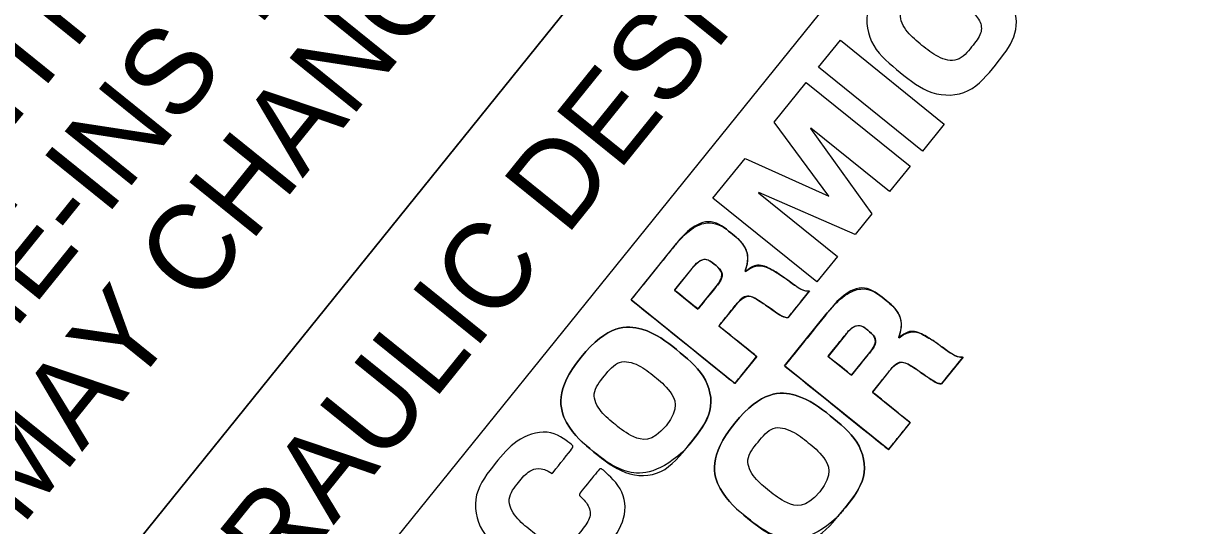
# Model space of a CAD drawing. Extents: x 1487832 to 1490056, y 498345 to 500343.
# Drawn here: x 1489651.2 to 1489727.7, y 499640.6 to 499673.5 of the extents above; entities that cross this region are included whole.
import ezdxf

# ---------------------------------------------------------------- set-up
doc = ezdxf.new("R2010")
doc.units = 0
doc.layers.add('Prop Grid Mask', color=7, linetype='Continuous')
doc.layers.add('Prop Horizontal Alignment Curve and Spiral Data', color=7, linetype='Continuous')

msp = doc.modelspace()

# ---------------------------------------------------------------- linework, layer by layer
at = {"layer": 'Prop Grid Mask'}
for p, q in [((1489703.231, 499670.595), (1489704.659, 499672.365)), ((1489704.659, 499672.365), (1489711.454, 499666.885)), ((1489710.027, 499665.115), (1489703.231, 499670.595)), ((1489700.329, 499666.996), (1489702.433, 499669.604)), ((1489702.433, 499669.604), (1489709.228, 499664.124)), ((1489703.916, 499662.173), (1489700.329, 499666.996)), ((1489702.726, 499666.619), (1489702.711, 499666.6)), ((1489702.711, 499666.6), (1489706.718, 499661.012)), ((1489707.885, 499662.459), (1489702.726, 499666.619)), ((1489711.454, 499666.885), (1489710.027, 499665.115)), ((1489696.323, 499662.028), (1489698.426, 499664.636)), ((1489698.426, 499664.636), (1489703.9, 499662.153)), ((1489709.228, 499664.124), (1489707.885, 499662.459)), ((1489703.118, 499656.548), (1489696.323, 499662.028)), ((1489699.319, 499662.393), (1489699.303, 499662.374)), ((1489699.303, 499662.374), (1489704.462, 499658.214)), ((1489705.628, 499659.66), (1489699.319, 499662.393)), ((1489703.9, 499662.153), (1489703.916, 499662.173)), ((1489706.718, 499661.012), (1489705.628, 499659.66)), ((1489704.462, 499658.214), (1489703.118, 499656.548)), ((1489698.435, 499657.246), (1489698.454, 499657.231)), ((1489702.642, 499655.957), (1489701.23, 499654.207)), ((1489708.48, 499652.914), (1489708.499, 499652.899)), ((1489712.687, 499651.626), (1489711.275, 499649.875))]:
    msp.add_line(p, q, dxfattribs=at)
for points in [[(1489502.46, 499445.87), (1489705.455, 499697.585), (1489601.093, 499781.747), (1489398.098, 499530.033)], [(1489651.998, 499610.518), (1489715.609, 499689.396), (1489705.455, 499697.585), (1489641.844, 499618.707)], [(1489651.998, 499610.518), (1489715.609, 499689.396), (1489756.18, 499656.677), (1489692.569, 499577.8)]]:
    msp.add_lwpolyline(points, close=True, dxfattribs=at)
for points in [[(1489703.231, 499670.595), (1489704.659, 499672.365), (1489711.454, 499666.885), (1489710.027, 499665.115), (1489703.231, 499670.595)], [(1489696.323, 499662.028), (1489698.426, 499664.636), (1489703.9, 499662.153), (1489703.916, 499662.173), (1489700.329, 499666.996), (1489702.433, 499669.604), (1489709.228, 499664.124), (1489707.885, 499662.459), (1489702.726, 499666.619), (1489702.711, 499666.6), (1489706.718, 499661.012), (1489705.628, 499659.66), (1489699.319, 499662.393), (1489699.303, 499662.374), (1489704.462, 499658.214), (1489703.118, 499656.548), (1489696.323, 499662.028)], [(1489697.796, 499655.012), (1489696.713, 499653.67), (1489699.188, 499651.675), (1489697.761, 499649.904), (1489690.965, 499655.385), (1489693.759, 499658.849)], [(1489694.947, 499657.42), (1489693.811, 499656.011), (1489695.343, 499654.775), (1489696.54, 499656.26)], [(1489707.84, 499650.681), (1489706.758, 499649.339), (1489709.233, 499647.343), (1489707.805, 499645.573), (1489701.01, 499651.053), (1489703.804, 499654.517)], [(1489704.992, 499653.088), (1489703.855, 499651.68), (1489705.387, 499650.444), (1489706.585, 499651.929)]]:
    msp.add_lwpolyline(points, dxfattribs=at)
for points in [[(1489711.408, 499675.767), (1489710.645, 499676.223), (1489709.854, 499675.982), (1489709.255, 499675.24), (1489708.334, 499674.098), (1489708.989, 499672.847), (1489709.998, 499672.033), (1489711.007, 499671.219), (1489712.369, 499670.844), (1489713.29, 499671.986), (1489713.958, 499672.814), (1489713.866, 499673.673), (1489713.14, 499674.37), (1489713.14, 499674.37), (1489714.567, 499676.139), (1489714.567, 499676.139), (1489716.242, 499674.632), (1489716.233, 499672.519), (1489714.844, 499670.796), (1489713.186, 499668.74), (1489710.541, 499668.674), (1489708.571, 499670.263), (1489706.601, 499671.852), (1489706.105, 499674.451), (1489707.763, 499676.506), (1489708.945, 499677.972), (1489711.16, 499678.809), (1489712.835, 499677.537), (1489712.835, 499677.537), (1489711.408, 499675.767), (1489711.408, 499675.767)], [(1489711.408, 499675.767), (1489710.645, 499676.223), (1489709.854, 499675.982), (1489709.255, 499675.24), (1489708.334, 499674.098), (1489708.989, 499672.847), (1489709.998, 499672.033), (1489711.007, 499671.219), (1489712.369, 499670.844), (1489713.29, 499671.986), (1489713.958, 499672.814), (1489713.866, 499673.673), (1489713.14, 499674.37), (1489713.14, 499674.37), (1489714.567, 499676.139), (1489714.567, 499676.139), (1489716.242, 499674.632), (1489716.233, 499672.519), (1489714.844, 499670.796), (1489713.186, 499668.74), (1489710.541, 499668.674), (1489708.571, 499670.263), (1489706.601, 499671.852), (1489706.105, 499674.451), (1489707.763, 499676.506), (1489708.945, 499677.972), (1489711.16, 499678.809), (1489712.835, 499677.537), (1489712.835, 499677.537), (1489711.408, 499675.767), (1489711.408, 499675.767)], [(1489690.965, 499655.385), (1489690.965, 499655.385), (1489693.759, 499658.849), (1489693.759, 499658.849), (1489694.726, 499660.048), (1489696.22, 499660.791), (1489697.591, 499659.686), (1489698.324, 499659.094), (1489698.735, 499658.183), (1489698.435, 499657.246), (1489698.435, 499657.246), (1489698.454, 499657.231), (1489698.454, 499657.231), (1489699.209, 499657.816), (1489700.186, 499657.373), (1489700.88, 499656.908), (1489701.181, 499656.697), (1489702.203, 499655.919), (1489702.642, 499655.957), (1489702.642, 499655.957), (1489701.23, 499654.207), (1489701.23, 499654.207), (1489700.879, 499654.238), (1489700.189, 499654.747), (1489699.984, 499654.881), (1489699.26, 499655.386), (1489698.463, 499655.84), (1489697.796, 499655.012), (1489697.796, 499655.012), (1489696.713, 499653.67), (1489696.713, 499653.67), (1489696.713, 499653.67), (1489699.188, 499651.675), (1489699.188, 499651.675), (1489699.188, 499651.675), (1489697.761, 499649.904), (1489697.761, 499649.904), (1489697.761, 499649.904), (1489690.965, 499655.385), (1489690.965, 499655.385)], [(1489693.759, 499658.849), (1489694.726, 499660.048), (1489696.22, 499660.791), (1489697.591, 499659.686), (1489698.324, 499659.094), (1489698.735, 499658.183), (1489698.435, 499657.246)], [(1489695.343, 499654.775), (1489695.343, 499654.775), (1489696.54, 499656.26), (1489696.54, 499656.26), (1489696.97, 499656.793), (1489696.915, 499657.309), (1489696.401, 499657.724), (1489695.897, 499658.131), (1489695.346, 499657.915), (1489694.947, 499657.42), (1489694.947, 499657.42), (1489693.811, 499656.011), (1489693.811, 499656.011), (1489693.811, 499656.011), (1489695.343, 499654.775), (1489695.343, 499654.775)], [(1489696.54, 499656.26), (1489696.97, 499656.793), (1489696.915, 499657.309), (1489696.401, 499657.724), (1489695.897, 499658.131), (1489695.346, 499657.915), (1489694.947, 499657.42)], [(1489698.454, 499657.231), (1489699.209, 499657.816), (1489700.186, 499657.373), (1489700.88, 499656.908), (1489701.181, 499656.697), (1489702.203, 499655.919), (1489702.642, 499655.957)], [(1489701.23, 499654.207), (1489700.879, 499654.238), (1489700.189, 499654.747), (1489699.984, 499654.881), (1489699.26, 499655.386), (1489698.463, 499655.84), (1489697.796, 499655.012)], [(1489701.01, 499651.053), (1489701.01, 499651.053), (1489703.804, 499654.517), (1489703.804, 499654.517), (1489704.771, 499655.717), (1489706.265, 499656.46), (1489707.635, 499655.354), (1489708.368, 499654.763), (1489708.779, 499653.851), (1489708.48, 499652.914), (1489708.48, 499652.914), (1489708.499, 499652.899), (1489708.499, 499652.899), (1489709.253, 499653.484), (1489710.231, 499653.041), (1489710.924, 499652.576), (1489711.225, 499652.365), (1489712.247, 499651.588), (1489712.687, 499651.626), (1489712.687, 499651.626), (1489711.275, 499649.875), (1489711.275, 499649.875), (1489710.923, 499649.907), (1489710.234, 499650.415), (1489710.028, 499650.55), (1489709.305, 499651.055), (1489708.508, 499651.509), (1489707.84, 499650.681), (1489707.84, 499650.681), (1489706.758, 499649.339), (1489706.758, 499649.339), (1489706.758, 499649.339), (1489709.233, 499647.343), (1489709.233, 499647.343), (1489709.233, 499647.343), (1489707.805, 499645.573), (1489707.805, 499645.573), (1489707.805, 499645.573), (1489701.01, 499651.053), (1489701.01, 499651.053)], [(1489703.804, 499654.517), (1489704.771, 499655.717), (1489706.265, 499656.46), (1489707.635, 499655.354), (1489708.368, 499654.763), (1489708.779, 499653.851), (1489708.48, 499652.914)], [(1489687.696, 499651.624), (1489689.423, 499653.765), (1489691.969, 499653.707), (1489693.939, 499652.119), (1489695.909, 499650.53), (1489696.504, 499648.055), (1489694.777, 499645.913), (1489693.05, 499643.772), (1489690.506, 499643.829), (1489688.535, 499645.418), (1489686.565, 499647.007), (1489685.969, 499649.482), (1489687.696, 499651.624)], [(1489687.696, 499651.624), (1489689.423, 499653.765), (1489691.969, 499653.707), (1489693.939, 499652.119), (1489695.909, 499650.53), (1489696.504, 499648.055), (1489694.777, 499645.913), (1489694.541, 499645.62), (1489694.289, 499645.368), (1489694.025, 499645.156)], [(1489705.387, 499650.444), (1489705.387, 499650.444), (1489706.585, 499651.929), (1489706.585, 499651.929), (1489707.015, 499652.462), (1489706.96, 499652.977), (1489706.446, 499653.392), (1489705.941, 499653.799), (1489705.391, 499653.583), (1489704.992, 499653.088), (1489704.992, 499653.088), (1489703.855, 499651.68), (1489703.855, 499651.68), (1489703.855, 499651.68), (1489705.387, 499650.444), (1489705.387, 499650.444)], [(1489706.585, 499651.929), (1489707.015, 499652.462), (1489706.96, 499652.977), (1489706.446, 499653.392), (1489705.941, 499653.799), (1489705.391, 499653.583), (1489704.992, 499653.088)], [(1489708.499, 499652.899), (1489709.253, 499653.484), (1489710.231, 499653.041), (1489710.924, 499652.576), (1489711.225, 499652.365), (1489712.247, 499651.588), (1489712.687, 499651.626)], [(1489694.025, 499645.156), (1489692.364, 499643.816), (1489690.236, 499644.047), (1489688.535, 499645.418), (1489686.565, 499647.007), (1489685.969, 499649.482), (1489687.696, 499651.624)], [(1489693.255, 499647.141), (1489694.176, 499648.283), (1489693.52, 499649.535), (1489692.511, 499650.349), (1489691.502, 499651.162), (1489690.14, 499651.538), (1489689.219, 499650.396), (1489688.298, 499649.253), (1489688.954, 499648.002), (1489689.963, 499647.189), (1489690.972, 499646.375), (1489692.334, 499645.999), (1489693.255, 499647.141)], [(1489693.255, 499647.141), (1489694.176, 499648.283), (1489693.52, 499649.535), (1489692.511, 499650.349), (1489691.502, 499651.162), (1489690.14, 499651.538), (1489689.219, 499650.396), (1489688.298, 499649.253), (1489688.954, 499648.002), (1489689.963, 499647.189), (1489690.972, 499646.375), (1489692.334, 499645.999), (1489693.255, 499647.141)], [(1489711.275, 499649.875), (1489710.923, 499649.907), (1489710.234, 499650.415), (1489710.028, 499650.55), (1489709.305, 499651.055), (1489708.508, 499651.509), (1489707.84, 499650.681)], [(1489697.748, 499647.301), (1489699.475, 499649.443), (1489702.021, 499649.385), (1489703.991, 499647.797), (1489705.961, 499646.207), (1489706.557, 499643.732), (1489704.83, 499641.591), (1489703.103, 499639.449), (1489700.558, 499639.507), (1489698.587, 499641.096), (1489696.617, 499642.685), (1489696.021, 499645.16), (1489697.748, 499647.301)], [(1489697.748, 499647.301), (1489699.475, 499649.443), (1489702.021, 499649.385), (1489703.991, 499647.797), (1489705.961, 499646.207), (1489706.557, 499643.732), (1489704.83, 499641.591), (1489704.593, 499641.297), (1489704.341, 499641.045), (1489704.078, 499640.833)], [(1489685.807, 499644.021), (1489685.045, 499644.479), (1489684.253, 499644.237), (1489683.654, 499643.495), (1489682.733, 499642.353), (1489683.389, 499641.102), (1489684.398, 499640.288), (1489685.407, 499639.475), (1489686.769, 499639.099), (1489687.69, 499640.241), (1489688.358, 499641.069), (1489688.266, 499641.928), (1489687.539, 499642.624), (1489687.539, 499642.624), (1489688.967, 499644.395), (1489688.967, 499644.395), (1489690.641, 499642.887), (1489690.632, 499640.774), (1489689.243, 499639.051), (1489687.585, 499636.995), (1489684.941, 499636.929), (1489682.97, 499638.518), (1489681, 499640.106), (1489680.504, 499642.705), (1489682.162, 499644.761), (1489683.344, 499646.227), (1489685.559, 499647.064), (1489687.234, 499645.792), (1489687.234, 499645.792), (1489685.807, 499644.021), (1489685.807, 499644.021)], [(1489685.807, 499644.021), (1489685.045, 499644.479), (1489684.253, 499644.237), (1489683.654, 499643.495), (1489682.733, 499642.353), (1489683.389, 499641.102), (1489684.398, 499640.288), (1489685.407, 499639.475), (1489686.769, 499639.099), (1489687.69, 499640.241), (1489688.358, 499641.069), (1489688.266, 499641.928), (1489687.539, 499642.624), (1489687.539, 499642.624), (1489688.967, 499644.395), (1489688.967, 499644.395), (1489690.641, 499642.887), (1489690.632, 499640.774), (1489689.243, 499639.051), (1489687.585, 499636.995), (1489684.941, 499636.929), (1489682.97, 499638.518), (1489681, 499640.106), (1489680.504, 499642.705), (1489682.162, 499644.761), (1489683.344, 499646.227), (1489685.559, 499647.064), (1489687.234, 499645.792), (1489687.234, 499645.792), (1489685.807, 499644.021), (1489685.807, 499644.021)], [(1489704.078, 499640.833), (1489702.417, 499639.494), (1489700.288, 499639.724), (1489698.587, 499641.096), (1489696.617, 499642.685), (1489696.021, 499645.16), (1489697.748, 499647.301)], [(1489703.307, 499642.819), (1489704.228, 499643.961), (1489703.572, 499645.213), (1489702.563, 499646.026), (1489701.554, 499646.84), (1489700.193, 499647.215), (1489699.271, 499646.073), (1489698.35, 499644.931), (1489699.006, 499643.68), (1489700.015, 499642.866), (1489701.024, 499642.053), (1489702.386, 499641.677), (1489703.307, 499642.819)], [(1489703.307, 499642.819), (1489704.228, 499643.961), (1489703.572, 499645.213), (1489702.563, 499646.026), (1489701.554, 499646.84), (1489700.193, 499647.215), (1489699.271, 499646.073), (1489698.35, 499644.931), (1489699.006, 499643.68), (1489700.015, 499642.866), (1489701.024, 499642.053), (1489702.386, 499641.677), (1489703.307, 499642.819)]]:
    msp.add_open_spline(points, degree=3, dxfattribs=at)

# ---------------------------------------------------------------- texts
msp.add_text('919.223.8965   NC LIC. NO. F-1285', height=4.17727, rotation=51.11565, dxfattribs=at).set_placement((1489691.945, 499580.199))
at = {"layer": 'Prop Horizontal Alignment Curve and Spiral Data'}
for s, p in [('PLAN SET BEFORE START OF CONSTRUCTION. ANY DISCREPANCIES SHALL', (1489488.399, 499492.532)), ('ELEVATIONS POST NEW CROSSING  PANEL INSTALLATION.  CONTRACTOR', (1489501.534, 499481.939)), ('BE BROUGHT TO THE ATTENTION OF CSX.  FIELD VERIFY TOP OF RAIL', (1489494.966, 499487.235)), ('HYDRAULIC DESIGN', (1489658.114, 499624.012)), ('TO FIELD ADJUST PROFILE AT DIRECTION OF ENGINEER AT TIE-INS TO', (1489508.102, 499476.642)), ('THE NEW CROSSING SURFACE PANEL AS THE ELEVATION MAY CHANGE.', (1489514.67, 499471.346))]:
    msp.add_text(s, height=5.625, rotation=51.11565, dxfattribs=at).set_placement(p)

doc.saveas('drawing.dxf')
